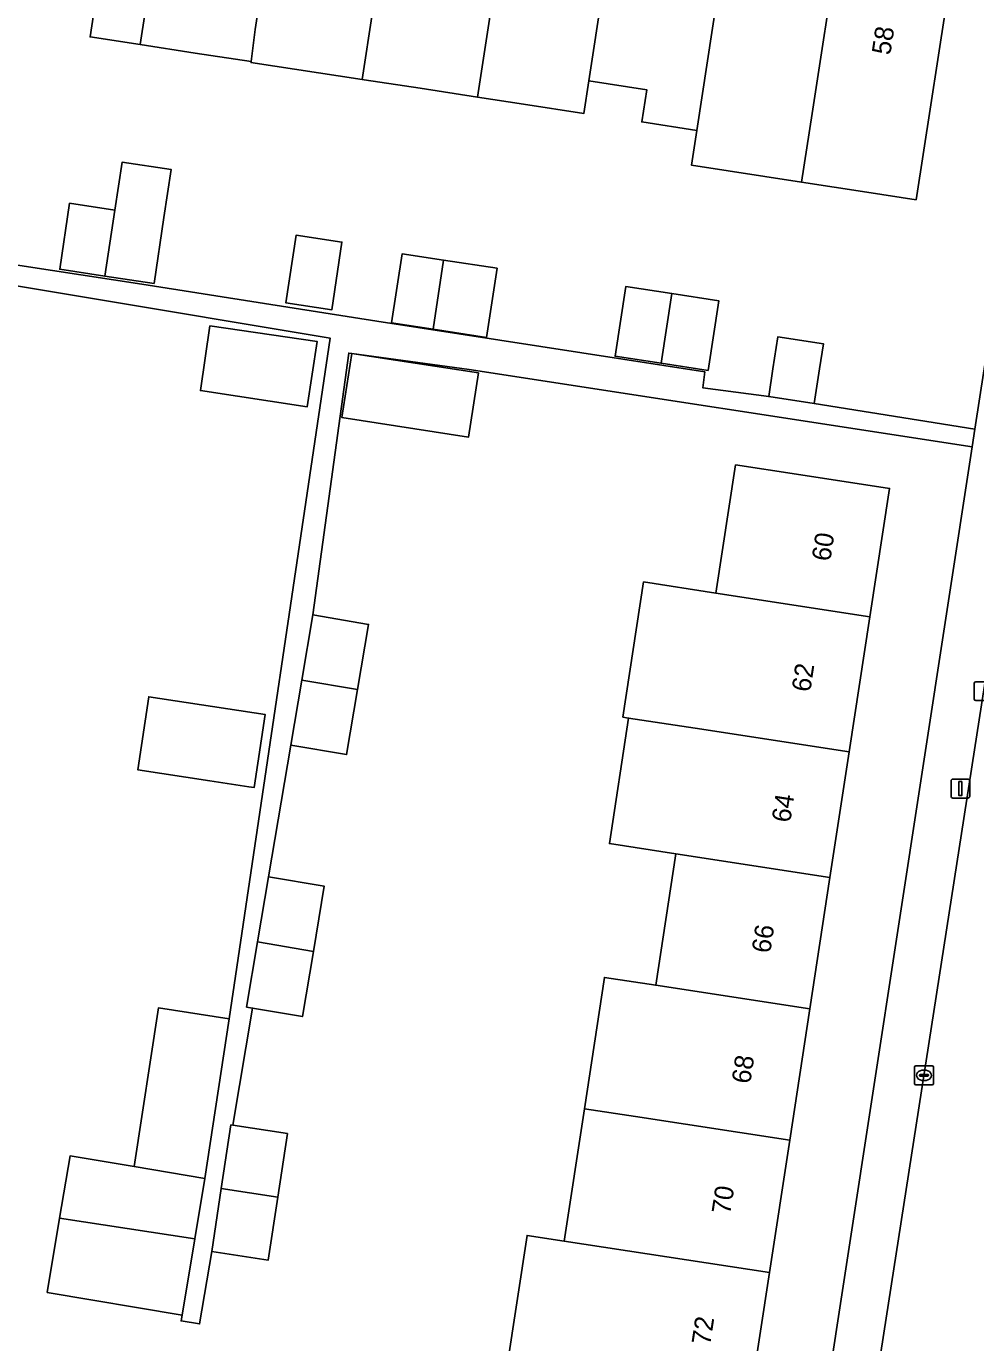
# Model space of a CAD drawing. Extents: x 161483 to 162250, y 379484 to 380833.
# Drawn here: x 161947.2 to 161997.6, y 380448.4 to 380518.2 of the extents above; entities that cross this region are included whole.
import ezdxf

# ---------------------------------------------------------------- set-up
doc = ezdxf.new("R2010")
doc.units = 0
for name, color, linetype in [('IMGEO_Erf', 7, 'Continuous'), ('IMGEO_Kolk', 7, 'Continuous'), ('IMGEO_Lichtmast', 7, 'Continuous'), ('IMGEO_Pand', 7, 'Continuous'), ('IMGEO_Pand_nummerreeks', 7, 'Continuous'), ('IMGEO_Rijbaan_lokaal_open', 7, 'Continuous'), ('IMGEO_Voetpad_open', 7, 'Continuous')]:
    doc.layers.add(name, color=color, linetype=linetype)

msp = doc.modelspace()

# ---------------------------------------------------------------- linework, layer by layer
at = {"layer": 'IMGEO_Erf'}
for points in [[(161996.342, 380521.448), (161994.423, 380508.962), (161991.806, 380509.364), (161988.352, 380509.895), (161982.508, 380510.793), (161982.791, 380512.634), (161979.877, 380513.082), (161980.139, 380514.792), (161977.073, 380515.263), (161976.807, 380513.532), (161973.602, 380514.024), (161971.173, 380514.397), (161968.125, 380514.865), (161965.15, 380515.316), (161965.048, 380515.332), (161959.156, 380516.237), (161959.162, 380516.28), (161956.197, 380516.736), (161953.288, 380517.183), (161950.629, 380517.592), (161950.898, 380519.337)], [(161963.35, 380501.629), (161923.518, 380508.257)], [(161942.146, 380506.198), (161953.363, 380504.486), (161959.871, 380503.456), (161965.827, 380502.514), (161983.214, 380499.84), (161983.127, 380499.132), (161983.106, 380498.993), (161986.607, 380498.522), (161986.833, 380500), (161987.093, 380501.694), (161989.505, 380501.325), (161989.302, 380500), (161989.019, 380498.153), (161997.539, 380496.804), (161998.03, 380500)], [(161982.918, 380401.702), (161997.393, 380495.855), (161970.721, 380499.955), (161964.501, 380500.811), (161964.341, 380500.833), (161962.43, 380486.949), (161965.388, 380486.451), (161964.807, 380482.999), (161964.226, 380479.548), (161961.267, 380480.046), (161960.087, 380473.066), (161963.046, 380472.568), (161962.465, 380469.117), (161961.884, 380465.665), (161959.246, 380466.109), (161958.201, 380459.901), (161961.093, 380459.461), (161960.579, 380456.088), (161960.072, 380452.753), (161957.075, 380453.209), (161956.428, 380449.367), (161955.449, 380449.532), (161955.501, 380449.842), (161948.352, 380451.041), (161949.013, 380454.981), (161949.566, 380458.278), (161952.966, 380457.708), (161954.247, 380466.123), (161958.004, 380465.551), (161963.35, 380501.629)], [(161972.74, 380447.152), (161973.799, 380454.063), (161975.755, 380453.763), (161976.831, 380460.778), (161977.898, 380467.74), (161980.62, 380467.323), (161981.688, 380474.288), (161978.158, 380474.829), (161979.179, 380481.488), (161978.878, 380481.534), (161979.976, 380488.697), (161983.806, 380488.11), (161984.848, 380494.904), (161988.071, 380494.41), (161993.013, 380493.653), (161991.971, 380486.858), (161990.873, 380479.695), (161989.853, 380473.036), (161988.785, 380466.071), (161987.718, 380459.109), (161986.642, 380452.095), (161985.583, 380445.183)]]:
    msp.add_lwpolyline(points, dxfattribs=at)
for points in [[(161954.543, 380508.021), (161954.021, 380504.522), (161951.405, 380504.913), (161949.015, 380505.27), (161949.537, 380508.769), (161951.942, 380508.409), (161952.332, 380510.951), (161954.922, 380510.564)], [(161963.981, 380506.714), (161963.444, 380503.125), (161961.01, 380503.488), (161961.546, 380507.078)], [(161969.373, 380505.762), (161972.204, 380505.327), (161971.64, 380501.664), (161968.81, 380502.1), (161966.611, 380502.438), (161967.175, 380506.1)], [(161983.959, 380503.606), (161983.39, 380499.908), (161980.896, 380500.292), (161978.464, 380500.666), (161979.033, 380504.364), (161981.465, 380503.99)], [(161956.478, 380498.844), (161956.982, 380502.274), (161962.668, 380501.438), (161962.135, 380497.974)], [(161964.501, 380500.811), (161971.216, 380499.778), (161970.693, 380496.377), (161963.978, 380497.41)], [(161953.739, 380482.61), (161959.915, 380481.67), (161959.327, 380477.806), (161959.05, 380477.848), (161956.983, 380478.163), (161953.151, 380478.746)]]:
    msp.add_lwpolyline(points, close=True, dxfattribs=at)
at = {"layer": 'IMGEO_Kolk'}
for p, q in [((161997.504, 380482.484), (161997.504, 380483.336)), ((161997.579, 380483.41), (161998.431, 380483.41)), ((161998.431, 380482.41), (161997.579, 380482.41)), ((161994.338, 380462.122), (161994.338, 380462.974)), ((161994.413, 380463.048), (161995.265, 380463.048)), ((161994.826, 380462.828), (161994.851, 380462.828)), ((161995.339, 380462.974), (161995.339, 380462.122)), ((161994.597, 380462.542), (161994.597, 380462.554)), ((161995.035, 380462.505), (161994.637, 380462.505)), ((161994.64, 380462.591), (161995.038, 380462.591)), ((161994.849, 380462.268), (161994.824, 380462.268)), ((161995.081, 380462.554), (161995.081, 380462.542)), ((161995.265, 380462.048), (161994.413, 380462.048))]:
    msp.add_line(p, q, dxfattribs=at)
for points in [[(161997.504, 380482.484), (161997.504, 380483.336)], [(161997.579, 380483.41), (161998.431, 380483.41)], [(161998.431, 380482.41), (161997.579, 380482.41)], [(161994.338, 380462.122), (161994.338, 380462.974)], [(161994.413, 380463.048), (161995.265, 380463.048)], [(161995.339, 380462.974), (161995.339, 380462.122)], [(161995.265, 380462.048), (161994.413, 380462.048)]]:
    msp.add_lwpolyline(points, dxfattribs=at)
for centre, radius, start, end in [((161997.581, 380483.334), 0.0765, 91.55205, 178.44795), ((161997.581, 380483.334), 0.0765, 91.55205, 178.44795), ((161997.581, 380482.486), 0.0765, 181.55205, 268.44795), ((161997.581, 380482.486), 0.0765, 181.55205, 268.44795), ((161994.415, 380462.972), 0.0765, 91.55205, 178.44795), ((161994.415, 380462.972), 0.0765, 91.55205, 178.44795), ((161995.263, 380462.972), 0.0765, 1.55205, 88.44795), ((161995.263, 380462.972), 0.0765, 1.55205, 88.44795), ((161994.415, 380462.124), 0.0765, 181.55205, 268.44795), ((161994.415, 380462.124), 0.0765, 181.55205, 268.44795), ((161994.637, 380462.551), 0.0403, 85.87752, 175.75265), ((161994.634, 380462.541), 0.0366, 178.93798, 274.71019), ((161995.038, 380462.548), 0.043, 264.86636, 352.45326), ((161995.042, 380462.553), 0.0386, 1.73085, 96.63898), ((161995.263, 380462.124), 0.0765, 271.55205, 358.44795), ((161995.263, 380462.124), 0.0765, 271.55205, 358.44795)]:
    msp.add_arc(centre, radius, start, end, dxfattribs=at)
for centre, major_axis, ratio, start_param, end_param in [((161994.825, 380462.548), (-0.387, 0.002), 0.722429, 4.712389, 7.853982), ((161994.85, 380462.548), (-0.39, 0.002), 0.717154, 1.570796, 4.712389)]:
    msp.add_ellipse(centre, major_axis=major_axis, ratio=ratio, start_param=start_param, end_param=end_param, dxfattribs=at)
at = {"layer": 'IMGEO_Lichtmast'}
for p, q in [((161996.271, 380477.347), (161996.271, 380478.147)), ((161996.271, 380478.147), (161996.271, 380477.347)), ((161996.371, 380478.247), (161997.161, 380478.247)), ((161997.161, 380478.247), (161996.371, 380478.247)), ((161997.261, 380478.147), (161997.261, 380477.347)), ((161997.261, 380477.347), (161997.261, 380478.147)), ((161997.161, 380477.247), (161996.371, 380477.247)), ((161996.371, 380477.247), (161997.161, 380477.247))]:
    msp.add_line(p, q, dxfattribs=at)
msp.add_lwpolyline([(161996.691, 380478.122), (161996.841, 380478.122), (161996.841, 380477.372), (161996.691, 380477.372), (161996.691, 380478.122)], dxfattribs=at)
for centre, start, end in [((161996.371, 380478.147), 90, 180), ((161996.371, 380478.147), 90, 180), ((161997.161, 380478.147), 0, 90), ((161997.161, 380478.147), 360, 90), ((161996.371, 380477.347), 180, 270), ((161996.371, 380477.347), 180, 270), ((161997.161, 380477.347), 270, 0), ((161997.161, 380477.347), 270, 0)]:
    msp.add_arc(centre, 0.1, start, end, dxfattribs=at)
at = {"layer": 'IMGEO_Pand'}
for points in [[(161953.288, 380517.183), (161954.923, 380527.827), (161952.36, 380528.221), (161952.481, 380529.006), (161949.063, 380529.531), (161947.576, 380519.847), (161950.898, 380519.337), (161950.629, 380517.592)], [(161960.869, 380527.668), (161957.446, 380528.194), (161957.332, 380527.456), (161954.923, 380527.827), (161953.288, 380517.183), (161956.197, 380516.736), (161959.162, 380516.28), (161959.381, 380517.981)], [(161966.695, 380526.052), (161964.127, 380526.446), (161964.235, 380527.151), (161960.869, 380527.668), (161959.381, 380517.981), (161959.162, 380516.28), (161959.156, 380516.237), (161965.048, 380515.332)], [(161972.814, 380525.079), (161970.069, 380525.501), (161970.184, 380526.248), (161967.05, 380526.73), (161966.94, 380526.014), (161966.695, 380526.052), (161965.048, 380515.332), (161965.15, 380515.316), (161968.125, 380514.865), (161971.173, 380514.397)], [(161978.56, 380524.947), (161975.079, 380525.482), (161974.966, 380524.748), (161972.814, 380525.079), (161971.173, 380514.397), (161973.602, 380514.024), (161976.807, 380513.532), (161977.073, 380515.263)], [(161977.073, 380515.263), (161980.139, 380514.792), (161979.877, 380513.082), (161982.791, 380512.634), (161984.425, 380523.272), (161981.901, 380523.66), (161982.017, 380524.415), (161978.56, 380524.947)], [(161990.27, 380522.381), (161990.381, 380523.106), (161986.464, 380523.708), (161986.351, 380522.976), (161984.425, 380523.272), (161982.791, 380512.634), (161982.508, 380510.793), (161988.352, 380509.895), (161988.911, 380513.534)], [(161996.342, 380521.448), (161990.445, 380522.354), (161990.27, 380522.381), (161988.911, 380513.534), (161988.352, 380509.895), (161991.806, 380509.364), (161994.423, 380508.962)], [(161954.543, 380508.021), (161954.922, 380510.564), (161952.332, 380510.951), (161951.942, 380508.409), (161951.405, 380504.913), (161954.021, 380504.522)], [(161951.942, 380508.409), (161949.537, 380508.769), (161949.015, 380505.27), (161951.405, 380504.913)], [(161963.444, 380503.125), (161963.981, 380506.714), (161961.546, 380507.078), (161961.01, 380503.488)], [(161969.373, 380505.762), (161967.175, 380506.1), (161966.611, 380502.438), (161968.81, 380502.1)], [(161969.373, 380505.762), (161968.81, 380502.1), (161971.64, 380501.664), (161972.204, 380505.327)], [(161981.465, 380503.99), (161979.033, 380504.364), (161978.464, 380500.666), (161980.896, 380500.292)], [(161981.465, 380503.99), (161980.896, 380500.292), (161983.39, 380499.908), (161983.959, 380503.606)], [(161962.668, 380501.438), (161956.982, 380502.274), (161956.478, 380498.844), (161962.135, 380497.974)], [(161989.019, 380498.153), (161989.302, 380500), (161989.505, 380501.325), (161987.093, 380501.694), (161986.833, 380500), (161986.607, 380498.522)], [(161971.216, 380499.778), (161964.501, 380500.811), (161963.978, 380497.41), (161970.693, 380496.377)], [(161983.806, 380488.11), (161991.971, 380486.858), (161993.013, 380493.653), (161988.071, 380494.41), (161984.848, 380494.904)], [(161991.971, 380486.858), (161983.806, 380488.11), (161979.976, 380488.697), (161978.878, 380481.534), (161979.179, 380481.488), (161982.708, 380480.947), (161990.873, 380479.695)], [(161964.807, 380482.999), (161965.388, 380486.451), (161962.43, 380486.949), (161961.848, 380483.497)], [(161964.807, 380482.999), (161961.848, 380483.497), (161961.267, 380480.046), (161964.226, 380479.548)], [(161956.983, 380478.163), (161959.05, 380477.848), (161959.327, 380477.806), (161959.915, 380481.67), (161953.739, 380482.61), (161953.151, 380478.746)], [(161982.708, 380480.947), (161979.179, 380481.488), (161978.158, 380474.829), (161981.688, 380474.288), (161989.853, 380473.036), (161990.873, 380479.695)], [(161988.785, 380466.071), (161989.853, 380473.036), (161981.688, 380474.288), (161980.62, 380467.323)], [(161959.506, 380469.615), (161962.465, 380469.117), (161963.046, 380472.568), (161960.087, 380473.066)], [(161962.465, 380469.117), (161959.506, 380469.615), (161958.925, 380466.163), (161959.246, 380466.109), (161961.884, 380465.665)], [(161987.718, 380459.109), (161988.785, 380466.071), (161980.62, 380467.323), (161977.898, 380467.74), (161976.831, 380460.778), (161979.552, 380460.361)], [(161958.004, 380465.551), (161954.247, 380466.123), (161952.966, 380457.708), (161956.715, 380457.079)], [(161987.718, 380459.109), (161979.552, 380460.361), (161976.831, 380460.778), (161975.755, 380453.763), (161986.642, 380452.095)], [(161958.201, 380459.901), (161958.095, 380459.917), (161957.583, 380456.547), (161960.579, 380456.088), (161961.093, 380459.461)], [(161956.715, 380457.079), (161952.966, 380457.708), (161949.566, 380458.278), (161949.013, 380454.981), (161956.179, 380453.882)], [(161960.579, 380456.088), (161957.583, 380456.547), (161957.075, 380453.209), (161960.072, 380452.753)], [(161956.179, 380453.882), (161949.013, 380454.981), (161948.352, 380451.041), (161955.501, 380449.842)], [(161972.74, 380447.152), (161985.583, 380445.183), (161986.642, 380452.095), (161975.755, 380453.763), (161973.799, 380454.063)]]:
    msp.add_lwpolyline(points, close=True, dxfattribs=at)
at = {"layer": 'IMGEO_Rijbaan_lokaal_open'}
msp.add_lwpolyline([(162005.978, 380491.592), (162006.784, 380496.829), (162007.271, 380500), (162009.728, 380516.285), (162010.756, 380522.832), (162010.932, 380524.02), (162005.085, 380524.854), (162004.891, 380523.86), (162003.878, 380516.894), (162001.249, 380500), (162000.753, 380496.771), (162000.066, 380492.294), (162000, 380492.002), (161999.789, 380491.531), (161999.389, 380490.794), (161999.112, 380490.027), (161990.029, 380431.608)], dxfattribs=at)
at = {"layer": 'IMGEO_Voetpad_open'}
for points in [[(162005.228, 380525.716), (162000.674, 380526.189), (162001.144, 380525.735), (162001.658, 380524.62), (162001.728, 380523.906), (162000, 380512.813), (161998.03, 380500), (161997.539, 380496.804), (161997.393, 380495.855), (161982.918, 380401.702)], [(161990.029, 380431.608), (161999.112, 380490.027), (161999.389, 380490.794), (161999.789, 380491.531), (162000, 380492.002), (162000.066, 380492.294), (161999.572, 380492.37), (162000, 380495.135), (162000.265, 380496.846), (162000.753, 380496.771), (162001.249, 380500), (162003.878, 380516.894), (162004.891, 380523.86), (162005.085, 380524.854)], [(161962.43, 380486.949), (161964.341, 380500.833), (161964.501, 380500.811), (161970.721, 380499.955), (161997.393, 380495.855), (161997.539, 380496.804), (161989.019, 380498.153), (161986.607, 380498.522), (161983.106, 380498.993), (161983.127, 380499.132), (161983.214, 380499.84), (161965.827, 380502.514), (161959.871, 380503.456), (161953.363, 380504.486), (161942.146, 380506.198), (161939.653, 380506.621), (161937.159, 380507.044), (161933.658, 380507.603), (161927.487, 380508.552), (161923.628, 380509.209), (161923.552, 380508.732)], [(161923.518, 380508.257), (161963.35, 380501.629), (161958.004, 380465.551), (161956.715, 380457.079), (161956.179, 380453.882), (161955.501, 380449.842), (161955.449, 380449.532), (161956.428, 380449.367), (161957.075, 380453.209), (161957.583, 380456.547), (161958.095, 380459.917), (161958.201, 380459.901), (161959.246, 380466.109), (161958.925, 380466.163), (161959.506, 380469.615), (161960.087, 380473.066), (161961.267, 380480.046), (161961.848, 380483.497), (161962.43, 380486.949)]]:
    msp.add_lwpolyline(points, dxfattribs=at)

# ---------------------------------------------------------------- texts
at = {"layer": 'IMGEO_Pand_nummerreeks'}
for s, rotation, p in [('58', 81.2626, (161993.047, 380516.593)), ('60', 81.28479, (161989.867, 380489.759)), ('62', 81.28552, (161988.804, 380482.83)), ('64', 81.28479, (161987.744, 380475.909)), ('66', 81.28479, (161986.683, 380468.985)), ('68', 81.28479, (161985.621, 380462.064)), ('70', 81.28479, (161984.56, 380455.141)), ('72', 81.28479, (161983.498, 380448.211))]:
    msp.add_text(s, height=1, rotation=rotation, dxfattribs=at).set_placement(p)

doc.saveas('drawing.dxf')
